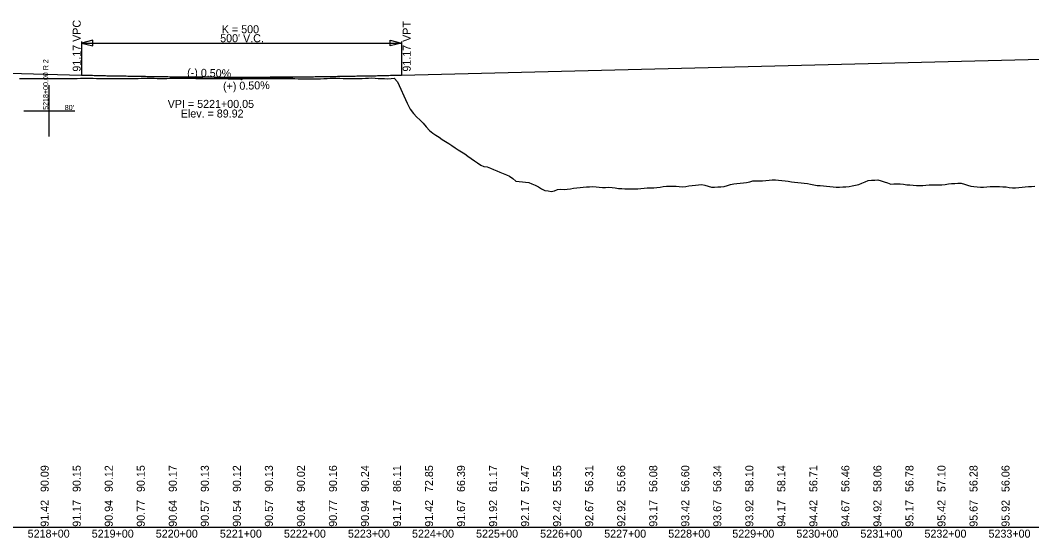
# Model space of a CAD drawing. Extents: x 2147288 to 2220488, y 740833 to 759333.
# Drawn here: x 2154136 to 2155715, y 758067 to 758875 of the extents above; entities that cross this region are included whole.
import ezdxf

# ---------------------------------------------------------------- set-up
doc = ezdxf.new("R2010")
doc.units = 0
for name, color, linetype in [('RD_DDB_GradeTX', 7, 'Continuous'), ('RD_DDB_Profile_EX', 7, 'Continuous'), ('RD_DDB_Profile_Lbl', 7, 'Continuous'), ('RD_DDB_Profile_PR', 7, 'Continuous'), ('RD_DDB_StaTX', 7, 'Continuous'), ('RD_DDB_StripGrade', 7, 'Continuous'), ('RD_DDB_VCLbl', 7, 'Continuous'), ('RD_GPK_Profile_Cell', 7, 'Continuous')]:
    doc.layers.add(name, color=color, linetype=linetype)

msp = doc.modelspace()

# ---------------------------------------------------------------- linework, layer by layer
at = {"layer": 'RD_DDB_GradeTX'}
for p, q in [((2154401.2, 758785), (2154480.1, 758783)), ((2154561.1, 758785), (2154482.1, 758783))]:
    msp.add_line(p, q, dxfattribs=at)
msp.add_circle((2154481.1, 758783), 1, dxfattribs=at)
at = {"layer": 'RD_DDB_Profile_EX'}
for points in [[(2154134.6, 758783.7), (2154139.6, 758783.7), (2154144.6, 758783.8), (2154149.6, 758783.8), (2154154.6, 758783.8), (2154159.6, 758783.8), (2154164.6, 758783.8), (2154169.6, 758783.8), (2154174.6, 758783.8), (2154179.6, 758783.8), (2154184.6, 758783.9), (2154189.6, 758783.9), (2154194.6, 758783.9), (2154199.6, 758783.9), (2154204.6, 758784), (2154209.6, 758784), (2154214.6, 758784.1), (2154219.6, 758784.1), (2154224.6, 758784.1), (2154229.6, 758784.2), (2154234.6, 758784.2), (2154239.6, 758784.2), (2154244.6, 758784.2), (2154249.6, 758784.2), (2154254.6, 758784.1), (2154259.6, 758784.1), (2154264.6, 758784.1), (2154269.6, 758784.1), (2154274.6, 758784.1), (2154279.6, 758784), (2154284.6, 758784), (2154289.6, 758784), (2154294.6, 758784), (2154299.6, 758784), (2154304.6, 758784.1), (2154309.6, 758784.1), (2154314.6, 758784.1), (2154319.6, 758784.1), (2154324.6, 758784.2), (2154329.6, 758784.2), (2154334.6, 758784.2), (2154339.6, 758784.2), (2154344.6, 758784.2), (2154349.6, 758784.1), (2154354.6, 758784.1), (2154359.6, 758784.1), (2154364.6, 758784.1), (2154369.6, 758784.2), (2154374.6, 758784.2), (2154379.6, 758784.3), (2154384.6, 758784.3), (2154389.6, 758784.4), (2154394.6, 758784.4), (2154399.6, 758784.4), (2154404.6, 758784.2), (2154409.6, 758784), (2154414.6, 758783.9), (2154419.6, 758784), (2154424.6, 758784), (2154429.6, 758784.1), (2154434.6, 758784.1), (2154439.6, 758784), (2154444.6, 758784), (2154449.6, 758784), (2154454.6, 758783.9), (2154459.6, 758783.9), (2154464.6, 758783.9), (2154469.6, 758783.9), (2154474.6, 758784), (2154479.6, 758784), (2154484.6, 758784), (2154489.6, 758784.1), (2154494.6, 758784.1), (2154499.6, 758784.1), (2154504.6, 758784.1), (2154509.6, 758784.1), (2154514.6, 758784.1), (2154519.6, 758784.1), (2154524.6, 758784.1), (2154529.6, 758784.1), (2154534.6, 758784)], [(2154534.6, 758784), (2154539.6, 758784), (2154544.6, 758783.9), (2154549.6, 758783.9), (2154554.6, 758783.8), (2154559.6, 758783.7), (2154564.6, 758783.7), (2154569.6, 758783.6), (2154574.6, 758783.6), (2154579.6, 758783.5), (2154584.6, 758783.5), (2154589.6, 758783.5), (2154594.6, 758783.4), (2154599.6, 758783.4), (2154604.6, 758783.5), (2154609.6, 758783.7), (2154614.6, 758784), (2154619.6, 758784.2), (2154624.6, 758784.3), (2154629.6, 758784.3), (2154634.6, 758784.2), (2154639.6, 758784.1), (2154644.6, 758784), (2154649.6, 758783.8), (2154654.6, 758783.7), (2154659.6, 758783.8), (2154664.6, 758783.9), (2154669.6, 758784.1), (2154674.6, 758784.4), (2154679.6, 758784.6), (2154684.6, 758784.8), (2154689.6, 758784.3), (2154694.6, 758783.9), (2154699.6, 758784), (2154704.6, 758783.7), (2154709.6, 758783.3), (2154714.6, 758783.7), (2154719.6, 758784.5), (2154724.6, 758778.6), (2154729.6, 758767), (2154734.6, 758756.9), (2154739.6, 758745.5), (2154744.6, 758736.2), (2154749.6, 758729.2), (2154754.6, 758723.7), (2154759.6, 758719.4), (2154764.6, 758714.2), (2154769.6, 758708.5), (2154774.6, 758702.7), (2154779.6, 758698.7), (2154784.6, 758695.4), (2154789.6, 758692.1), (2154794.6, 758688.9), (2154799.6, 758685.6), (2154804.6, 758682.4), (2154809.6, 758679.1), (2154814.6, 758675.9), (2154819.6, 758672.7), (2154824.6, 758669.5), (2154829.6, 758666.5), (2154834.6, 758662.8), (2154839.6, 758659.2), (2154844.6, 758655.6), (2154849.6, 758652), (2154854.6, 758648.4), (2154859.6, 758646.4), (2154864.6, 758646.1), (2154869.6, 758644.1), (2154874.6, 758642), (2154879.6, 758639.9), (2154884.6, 758637.8), (2154889.6, 758635.7), (2154894.6, 758633.6), (2154899.6, 758631.5), (2154904.6, 758627.7), (2154909.6, 758623.8), (2154914.6, 758623.2), (2154919.6, 758622.6), (2154924.6, 758622), (2154929.6, 758621.3), (2154934.6, 758619.5), (2154939.6, 758617.5), (2154944.6, 758614.9), (2154949.6, 758611.7), (2154954.6, 758609.2), (2154959.6, 758608.4), (2154964.6, 758607.7), (2154969.6, 758608.5), (2154974.6, 758610.7), (2154979.6, 758611.4), (2154984.6, 758610.6), (2154989.6, 758610.9), (2154994.6, 758611.7), (2154999.6, 758612.5), (2155004.6, 758613.2), (2155009.6, 758613.9), (2155014.6, 758614.5), (2155019.6, 758614.9), (2155024.6, 758615), (2155029.6, 758615.1), (2155034.6, 758614.8)], [(2155034.6, 758614.8), (2155039.6, 758614.1), (2155044.6, 758613.5), (2155049.6, 758613.8), (2155054.6, 758614.1), (2155059.6, 758614), (2155064.6, 758613.2), (2155069.6, 758612.4), (2155074.6, 758612), (2155079.6, 758611.8), (2155084.6, 758611.6), (2155089.6, 758611.6), (2155094.6, 758611.8), (2155099.6, 758611.9), (2155104.6, 758612.3), (2155109.6, 758612.6), (2155114.6, 758613), (2155119.6, 758613.1), (2155124.6, 758613.2), (2155129.6, 758613.6), (2155134.6, 758614.4), (2155139.6, 758615.2), (2155144.6, 758615.7), (2155149.6, 758615.8), (2155154.6, 758616), (2155159.6, 758615.7), (2155164.6, 758615.3), (2155169.6, 758614.9), (2155174.6, 758615.3), (2155179.6, 758616.2), (2155184.6, 758617), (2155189.6, 758617.5), (2155194.6, 758618), (2155199.6, 758618.4), (2155204.6, 758617.5), (2155209.6, 758615.9), (2155214.6, 758614.3), (2155219.6, 758614.4), (2155224.6, 758614.7), (2155229.6, 758615), (2155234.6, 758615.5), (2155239.6, 758616.9), (2155244.6, 758618.4), (2155249.6, 758619.5), (2155254.6, 758620), (2155259.6, 758620.5), (2155264.6, 758621), (2155269.6, 758621.8), (2155274.6, 758622.8), (2155279.6, 758623.9), (2155284.6, 758624.1), (2155289.6, 758624.3), (2155294.6, 758624.4), (2155299.6, 758624.6), (2155304.6, 758625.1), (2155309.6, 758625.6), (2155314.6, 758625.8), (2155319.6, 758625.3), (2155324.6, 758624.8), (2155329.6, 758624.3), (2155334.6, 758623.6), (2155339.6, 758622.8), (2155344.6, 758622.1), (2155349.6, 758621.5), (2155354.6, 758621), (2155359.6, 758620.5), (2155364.6, 758619.9), (2155369.6, 758618.9), (2155374.6, 758617.9), (2155379.6, 758617.1), (2155384.6, 758616.7), (2155389.6, 758616.3), (2155394.6, 758615.9), (2155399.6, 758615.4), (2155404.6, 758614.8), (2155409.6, 758614.2), (2155414.6, 758614.4), (2155419.6, 758614.7), (2155424.6, 758615), (2155429.6, 758615.5), (2155434.6, 758616.4), (2155439.6, 758617.4), (2155444.6, 758618.6), (2155449.6, 758620.6), (2155454.6, 758622.5), (2155459.6, 758624.5), (2155464.6, 758625.4), (2155469.6, 758625.4), (2155474.6, 758625.5), (2155479.6, 758624.2), (2155484.6, 758622.6), (2155489.6, 758620.9), (2155494.6, 758619.2), (2155499.6, 758619.3), (2155504.6, 758619.4), (2155509.6, 758619.4), (2155514.6, 758618.8), (2155519.6, 758618.1), (2155524.6, 758617.7), (2155529.6, 758617.4), (2155534.6, 758617.1)], [(2155534.6, 758617.1), (2155539.6, 758616.9), (2155544.6, 758617.1), (2155549.6, 758617.5), (2155554.6, 758617.9), (2155559.6, 758617.9), (2155564.6, 758617.8), (2155569.6, 758617.7), (2155574.6, 758617.8), (2155579.6, 758618.6), (2155584.6, 758619.5), (2155589.6, 758620), (2155594.6, 758620.1), (2155599.6, 758620.3), (2155604.6, 758620.4), (2155609.6, 758619.2), (2155614.6, 758617.4), (2155619.6, 758615.9), (2155624.6, 758615.4), (2155629.6, 758614.9), (2155634.6, 758614.5), (2155639.6, 758614.4), (2155644.6, 758615), (2155649.6, 758615.4), (2155654.6, 758615.3), (2155659.6, 758615.2), (2155664.6, 758615.1), (2155669.6, 758615), (2155674.6, 758614.8), (2155679.6, 758614), (2155684.6, 758613), (2155689.6, 758613.2), (2155694.6, 758613.8), (2155699.6, 758614.4), (2155704.6, 758615), (2155709.6, 758615.1), (2155714.6, 758615.3), (2155719.6, 758616)]]:
    msp.add_lwpolyline(points, dxfattribs=at)
at = {"layer": 'RD_DDB_Profile_PR'}
for p, q in [((2154731.1, 758789.3), (2156331.1, 758829.3)), ((2154031.1, 758794.3), (2154231.1, 758789.3))]:
    msp.add_line(p, q, dxfattribs=at)
msp.add_spline([(2154231.1, 758789.3), (2154241.1, 758789), (2154251.1, 758788.8), (2154261.1, 758788.6), (2154271.1, 758788.3), (2154281.1, 758788.1), (2154291.1, 758787.9), (2154301.1, 758787.8), (2154311.1, 758787.6), (2154321.1, 758787.4), (2154331.1, 758787.3), (2154341.1, 758787.1), (2154351.1, 758787), (2154361.1, 758786.9), (2154371.1, 758786.7), (2154381.1, 758786.6), (2154391.1, 758786.5), (2154401.1, 758786.5), (2154411.1, 758786.4), (2154421.1, 758786.3), (2154431.1, 758786.3), (2154441.1, 758786.2), (2154451.1, 758786.2), (2154461.1, 758786.2), (2154471.1, 758786.1), (2154481.1, 758786.1), (2154491.1, 758786.1), (2154501.1, 758786.2), (2154511.1, 758786.2), (2154521.1, 758786.2), (2154531.1, 758786.3), (2154541.1, 758786.3), (2154551.1, 758786.4), (2154561.1, 758786.5), (2154571.1, 758786.5), (2154581.1, 758786.6), (2154591.1, 758786.7), (2154601.1, 758786.9), (2154611.1, 758787), (2154621.1, 758787.1), (2154631.1, 758787.3), (2154641.1, 758787.4), (2154651.1, 758787.6), (2154661.1, 758787.8), (2154671.1, 758787.9), (2154681.1, 758788.1), (2154691.1, 758788.3), (2154701.1, 758788.6), (2154711.1, 758788.8), (2154721.1, 758789), (2154731.1, 758789.3)], degree=3, dxfattribs=at)
at = {"layer": 'RD_DDB_VCLbl'}
for p, q in [((2154231.1, 758841.8), (2154231.1, 758789.3)), ((2154231.1, 758839.3), (2154731.1, 758839.3)), ((2154731.1, 758841.8), (2154731.1, 758789.3))]:
    msp.add_line(p, q, dxfattribs=at)
for points in [[(2154249.1, 758843.8), (2154231.1, 758839.3), (2154249.1, 758834.8)], [(2154713.1, 758843.8), (2154731.1, 758839.3), (2154713.1, 758834.8)]]:
    msp.add_lwpolyline(points, close=True, dxfattribs=at)
at = {"layer": 'RD_GPK_Profile_Cell'}
for p, q in [((2154181.1, 758693.4), (2154181.1, 758773.4)), ((2154141.1, 758733.4), (2154221.1, 758733.4)), ((2148888.3, 758083.4), (2165888.3, 758083.4))]:
    msp.add_line(p, q, dxfattribs=at)

# ---------------------------------------------------------------- texts
at = {"layer": 'RD_DDB_GradeTX'}
for s, rotation, p in [('(-) 0.50%', 358.5679, (2154396.1, 758787.1)), ('(+) 0.50%', 1.4321, (2154452.4, 758765.6))]:
    msp.add_text(s, height=12.5, rotation=rotation, dxfattribs=at).set_placement(p)
at = {"layer": 'RD_DDB_Profile_Lbl'}
for s, p in [('VPI = 5221+00.05', (2154365.9, 758738)), ('Elev. = 89.92', (2154386.3, 758723))]:
    msp.add_text(s, height=12.5, dxfattribs=at).set_placement(p)
at = {"layer": 'RD_DDB_StaTX'}
for s, p in [('5218+00', (2154147.3, 758067.2)), ('5219+00', (2154247.3, 758067.2)), ('5220+00', (2154347.3, 758067.2)), ('5221+00', (2154447.3, 758067.2)), ('5222+00', (2154547.3, 758067.2)), ('5223+00', (2154647.3, 758067.2)), ('5224+00', (2154747.3, 758067.2)), ('5225+00', (2154847.3, 758067.2)), ('5226+00', (2154947.3, 758067.2)), ('5227+00', (2155047.3, 758067.2)), ('5228+00', (2155147.3, 758067.2)), ('5229+00', (2155247.3, 758067.2)), ('5230+00', (2155347.3, 758067.2)), ('5231+00', (2155447.3, 758067.2)), ('5232+00', (2155547.3, 758067.2)), ('5233+00', (2155647.3, 758067.2))]:
    msp.add_text(s, height=12.5, dxfattribs=at).set_placement(p)
at = {"layer": 'RD_DDB_StripGrade'}
for s, p in [('91.17 VPC', (2154230.1, 758794.6)), ('91.17 VPT', (2154745.3, 758794.6)), ('90.09', (2154180.1, 758138.4)), ('90.15', (2154230.1, 758138.4)), ('90.12', (2154280.1, 758138.4)), ('90.15', (2154330.1, 758138.4)), ('90.17', (2154380.1, 758138.4)), ('90.13', (2154430.1, 758138.4)), ('90.12', (2154480.1, 758138.4)), ('90.13', (2154530.1, 758138.4)), ('90.02', (2154580.1, 758138.4)), ('90.16', (2154630.1, 758138.4)), ('90.24', (2154680.1, 758138.4)), ('86.11', (2154730.1, 758138.4)), ('72.85', (2154780.1, 758138.4)), ('66.39', (2154830.1, 758138.4)), ('61.17', (2154880.1, 758138.4)), ('57.47', (2154930.1, 758138.4)), ('55.55', (2154980.1, 758138.4)), ('56.31', (2155030.1, 758138.4)), ('55.66', (2155080.1, 758138.4)), ('56.08', (2155130.1, 758138.4)), ('56.60', (2155180.1, 758138.4)), ('56.34', (2155230.1, 758138.4)), ('58.10', (2155280.1, 758138.4)), ('58.14', (2155330.1, 758138.4)), ('56.71', (2155380.1, 758138.4)), ('56.46', (2155430.1, 758138.4)), ('58.06', (2155480.1, 758138.4)), ('56.78', (2155530.1, 758138.4)), ('57.10', (2155580.1, 758138.4)), ('56.28', (2155630.1, 758138.4)), ('56.06', (2155680.1, 758138.4)), ('91.42', (2154180.1, 758084.2)), ('91.17', (2154230.1, 758084.2)), ('90.94', (2154280.1, 758084.2)), ('90.77', (2154330.1, 758084.2)), ('90.64', (2154380.1, 758084.2)), ('90.57', (2154430.1, 758084.2)), ('90.54', (2154480.1, 758084.2)), ('90.57', (2154530.1, 758084.2)), ('90.64', (2154580.1, 758084.2)), ('90.77', (2154630.1, 758084.2)), ('90.94', (2154680.1, 758084.2)), ('91.17', (2154730.1, 758084.2)), ('91.42', (2154780.1, 758084.2)), ('91.67', (2154830.1, 758084.2)), ('91.92', (2154880.1, 758084.2)), ('92.17', (2154930.1, 758084.2)), ('92.42', (2154980.1, 758084.2)), ('92.67', (2155030.1, 758084.2)), ('92.92', (2155080.1, 758084.2)), ('93.17', (2155130.1, 758084.2)), ('93.42', (2155180.1, 758084.2)), ('93.67', (2155230.1, 758084.2)), ('93.92', (2155280.1, 758084.2)), ('94.17', (2155330.1, 758084.2)), ('94.42', (2155380.1, 758084.2)), ('94.67', (2155430.1, 758084.2)), ('94.92', (2155480.1, 758084.2)), ('95.17', (2155530.1, 758084.2)), ('95.42', (2155580.1, 758084.2)), ('95.67', (2155630.1, 758084.2)), ('95.92', (2155680.1, 758084.2))]:
    msp.add_text(s, height=12.5, rotation=90, dxfattribs=at).set_placement(p)
at = {"layer": 'RD_DDB_VCLbl'}
for s, p in [("500' V.C.", (2154447.8, 758840.5)), ('K = 500', (2154450.4, 758854.5))]:
    msp.add_text(s, height=12.5, dxfattribs=at).set_placement(p)
at = {"layer": 'RD_GPK_Profile_Cell'}
msp.add_text('5218+00.00 R 2', height=8, rotation=90, dxfattribs=at).set_placement((2154179.3, 758735))
msp.add_text("80'", height=8, dxfattribs=at).set_placement((2154205.2, 758734.6))

doc.saveas('drawing.dxf')
